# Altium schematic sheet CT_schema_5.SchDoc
size 522 x 390 mm
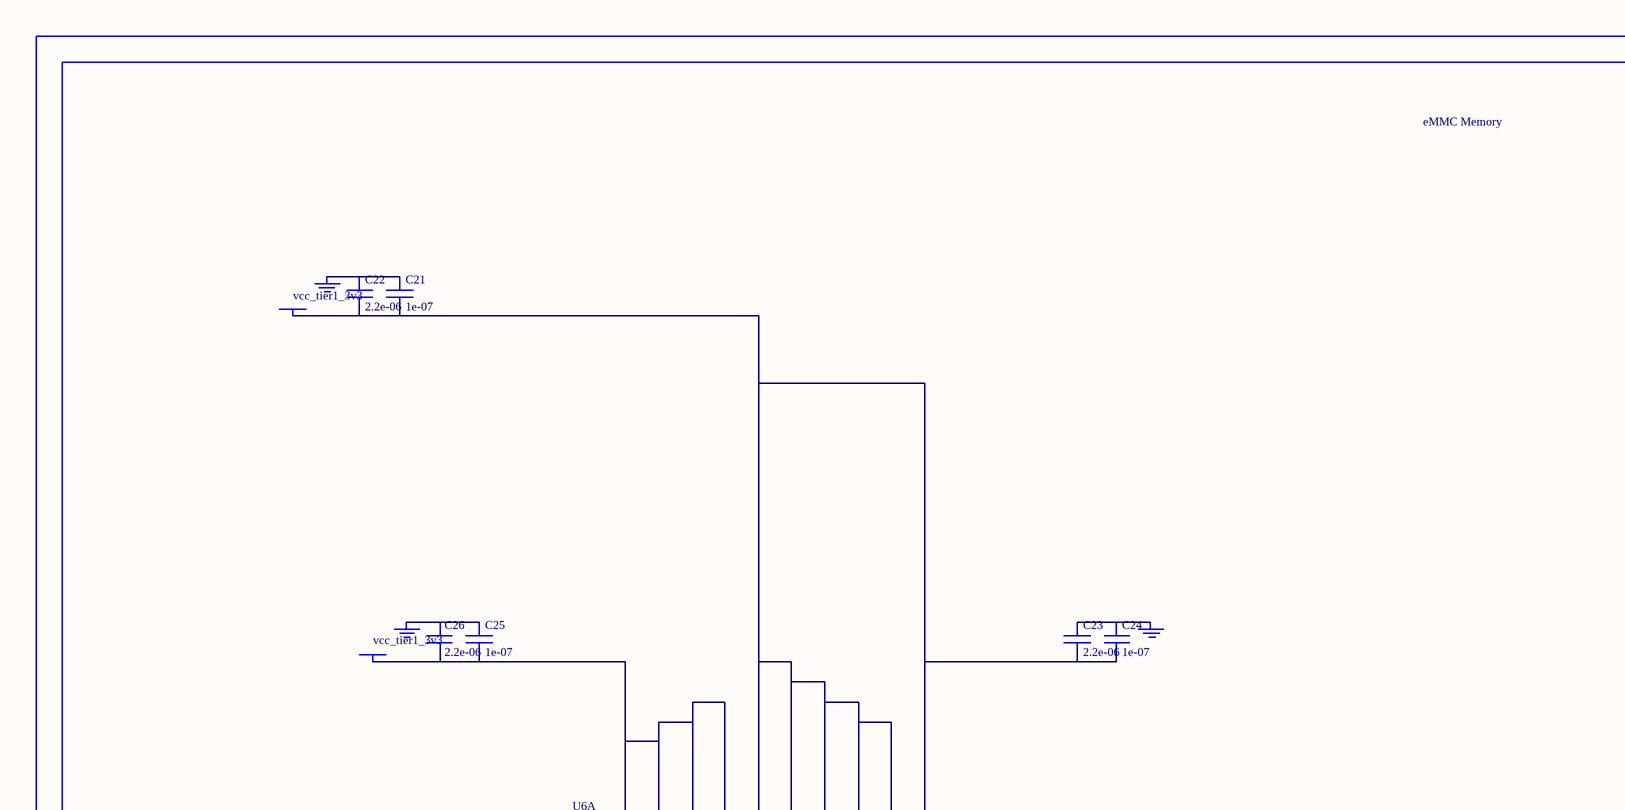
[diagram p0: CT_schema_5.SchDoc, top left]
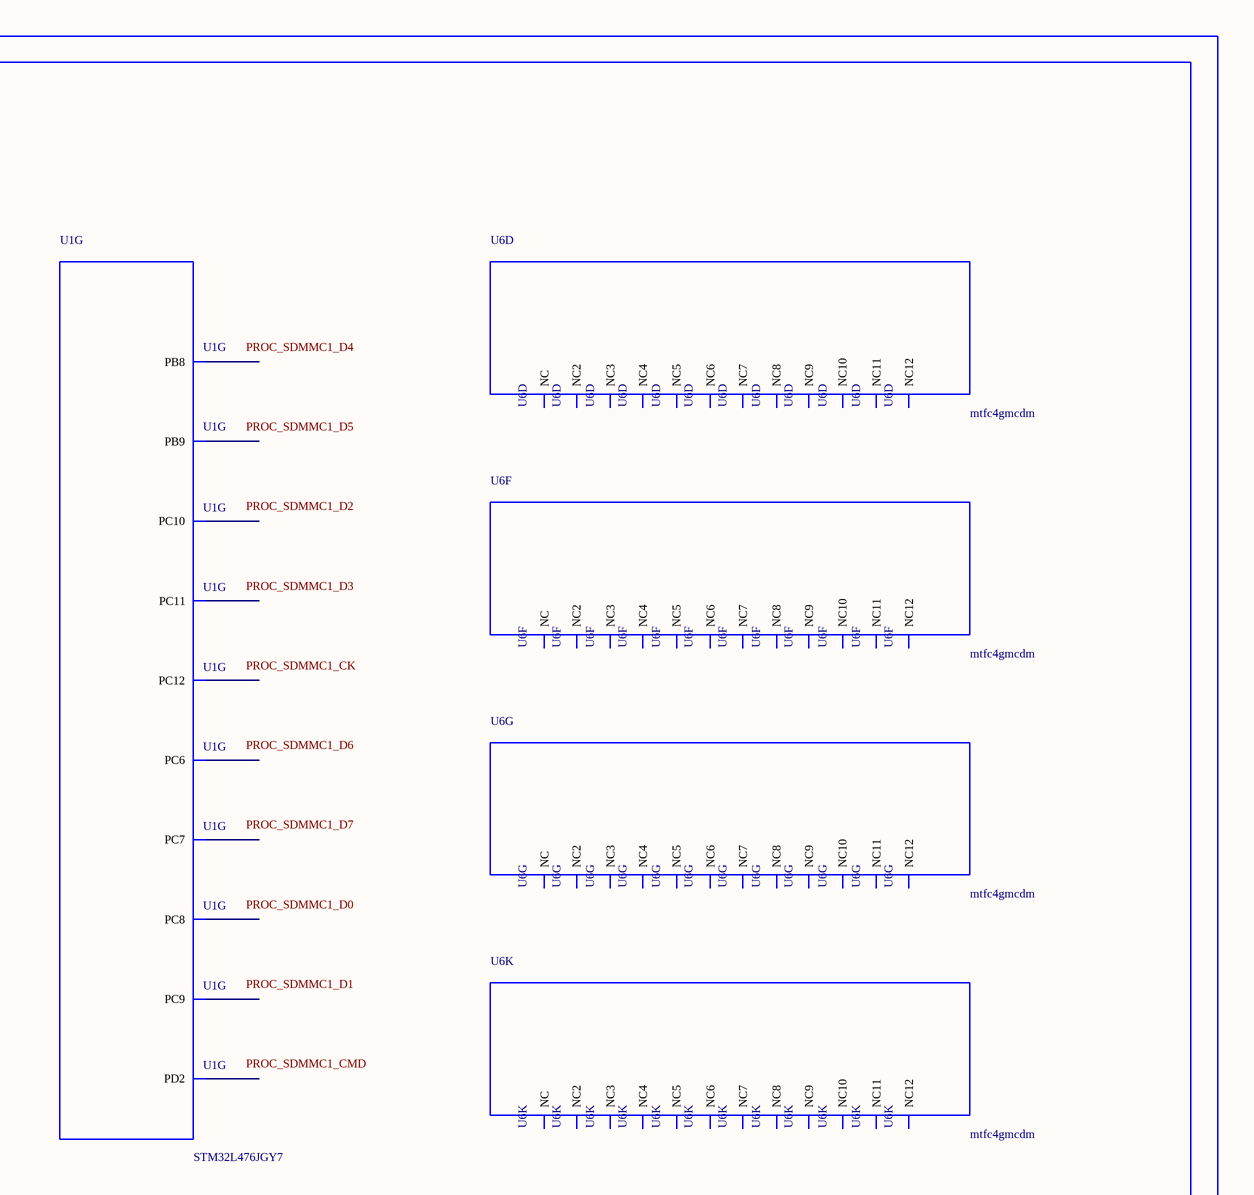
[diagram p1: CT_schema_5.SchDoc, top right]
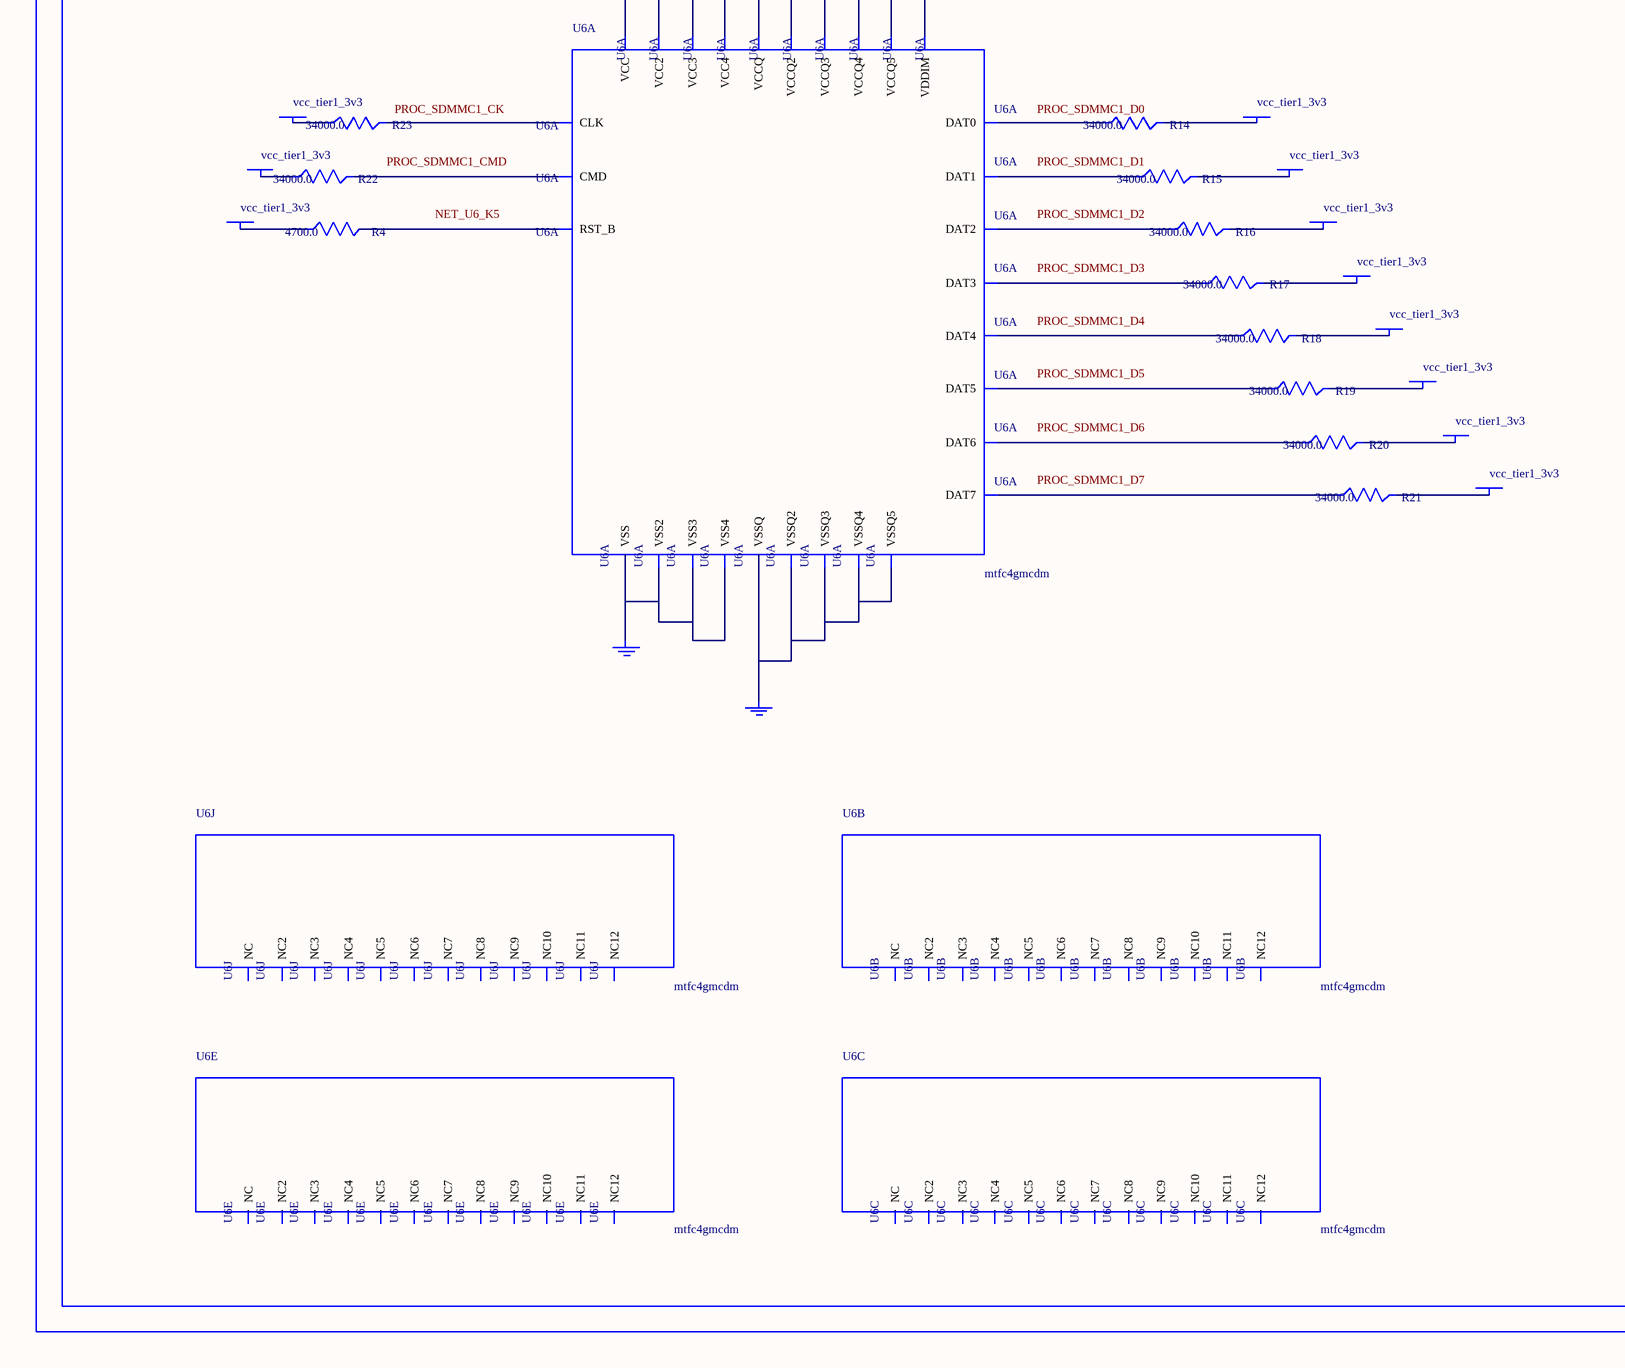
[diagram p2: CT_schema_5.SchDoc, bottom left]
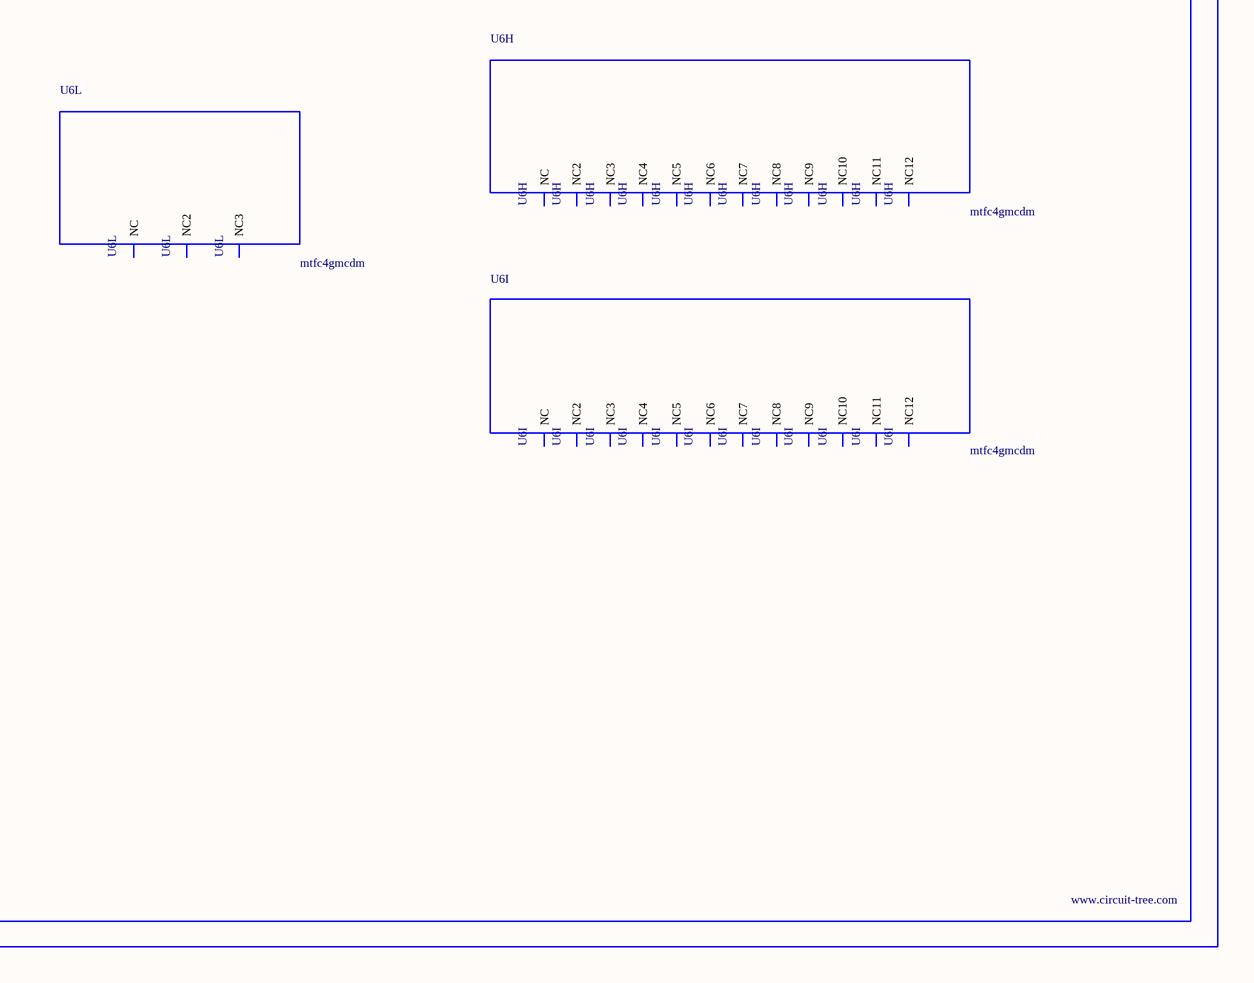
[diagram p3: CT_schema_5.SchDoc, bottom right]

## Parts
BORDER4  (no value)
C21  1e-07  [C0402]
C22  2.2e-06  [C0603]
C23  2.2e-06  [C0603]
C24  1e-07  [C0402]
C25  1e-07  [C0402]
C26  2.2e-06  [C0603]
GND_INSTANCE_4_0  (no value)
GND_INSTANCE_4_1  (no value)
GND_INSTANCE_4_2  (no value)
GND_INSTANCE_4_3  (no value)
GND_INSTANCE_4_4  (no value)
POWER_INSTANCE_4_0  vcc_tier1_3v3
POWER_INSTANCE_4_1  vcc_tier1_3v3
POWER_INSTANCE_4_2  vcc_tier1_3v3
POWER_INSTANCE_4_3  vcc_tier1_3v3
POWER_INSTANCE_4_4  vcc_tier1_3v3
POWER_INSTANCE_4_5  vcc_tier1_3v3
POWER_INSTANCE_4_6  vcc_tier1_3v3
POWER_INSTANCE_4_7  vcc_tier1_3v3
POWER_INSTANCE_4_8  vcc_tier1_3v3
POWER_INSTANCE_4_9  vcc_tier1_3v3
POWER_INSTANCE_4_10  vcc_tier1_3v3
POWER_INSTANCE_4_11  vcc_tier1_3v3
POWER_INSTANCE_4_12  vcc_tier1_3v3
R4  4700.0  [R0603]
R14  34000.0  [R0603]
R15  34000.0  [R0603]
R16  34000.0  [R0603]
R17  34000.0  [R0603]
R18  34000.0  [R0603]
R19  34000.0  [R0603]
R20  34000.0  [R0603]
R21  34000.0  [R0603]
R22  34000.0  [R0603]
R23  34000.0  [R0603]
U1  STM32L476JGY7  [WLCSP72]  (part G of 8)
U6  mtfc4gmcdm  [TFBGA-153]  (parts A,B,C,D,E,F,G,H,I,J,K,L of 12)

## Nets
NetC21_1: C21.1 C22.1 GND_INSTANCE_4_0.0(GND)
NetC21_2: C21.2 C22.2 C23.2 C24.2 POWER_INSTANCE_4_0.0(PWR) U6.C2(VDDIM) U6.C6(VCCQ) U6.M4(VCCQ2) U6.N4(VCCQ3) U6.P3(VCCQ4) U6.P5(VCCQ5)
NetC23_1: C23.1 C24.1 GND_INSTANCE_4_1.0(GND)
NetC25_1: C25.1 C26.1 GND_INSTANCE_4_2.0(GND)
NetC25_2: C25.2 C26.2 POWER_INSTANCE_4_1.0(PWR) U6.E6(VCC) U6.F5(VCC2) U6.J10(VCC3) U6.K9(VCC4)
NetGND_INSTANCE_4_3_0: GND_INSTANCE_4_3.0(GND) U6.E7(VSS) U6.G5(VSS2) U6.H10(VSS3) U6.K8(VSS4)
NetGND_INSTANCE_4_4_0: GND_INSTANCE_4_4.0(GND) U6.C4(VSSQ) U6.N2(VSSQ2) U6.N5(VSSQ3) U6.P4(VSSQ4) U6.P6(VSSQ5)
NetPOWER_INSTANCE_4_2_0: POWER_INSTANCE_4_2.0(PWR) R14.2
NetPOWER_INSTANCE_4_3_0: POWER_INSTANCE_4_3.0(PWR) R15.2
NetPOWER_INSTANCE_4_4_0: POWER_INSTANCE_4_4.0(PWR) R16.2
NetPOWER_INSTANCE_4_5_0: POWER_INSTANCE_4_5.0(PWR) R17.2
NetPOWER_INSTANCE_4_6_0: POWER_INSTANCE_4_6.0(PWR) R18.2
NetPOWER_INSTANCE_4_7_0: POWER_INSTANCE_4_7.0(PWR) R19.2
NetPOWER_INSTANCE_4_8_0: POWER_INSTANCE_4_8.0(PWR) R20.2
NetPOWER_INSTANCE_4_9_0: POWER_INSTANCE_4_9.0(PWR) R21.2
NetPOWER_INSTANCE_4_10_0: POWER_INSTANCE_4_10.0(PWR) R22.1
NetPOWER_INSTANCE_4_11_0: POWER_INSTANCE_4_11.0(PWR) R23.1
NetPOWER_INSTANCE_4_12_0: POWER_INSTANCE_4_12.0(PWR) R4.1
NetR4_2: R4.2 U6.K5(RST_B)
NetR14_1: R14.1 U6.A3(DAT0)
NetR15_1: R15.1 U6.A4(DAT1)
NetR16_1: R16.1 U6.A5(DAT2)
NetR17_1: R17.1 U6.B2(DAT3)
NetR18_1: R18.1 U6.B3(DAT4)
NetR19_1: R19.1 U6.B4(DAT5)
NetR20_1: R20.1 U6.B5(DAT6)
NetR21_1: R21.1 U6.B6(DAT7)
NetR22_2: R22.2 U6.M5(CMD)
NetR23_2: R23.2 U6.M6(CLK)

Not connected (* = marked no-connect by the designer): U1 A3(PD2) B3(PC12) C3(PC11) D3(PC10) E1(PC9) E7(PB8) E8(PB9) F1(PC7) F2(PC8) F3(PC6); U6 A1(NC) A2(NC7) A6(NC8) A7(NC9) A8(NC10) A9(NC11) A10(NC2) A11(NC3) A12(NC4) A13(NC5) A14(NC6) B1(NC12) B7(NC6) B8(NC7) B9(NC8) B10(NC) B11(NC2) B12(NC3) B13(NC4) B14(NC5) C1(NC9) C3(NC10) C5(NC11) C7(NC12) C8(NC6) C9(NC7) C10(NC) C11(NC2) C12(NC3) C13(NC4) C14(NC5) D1(NC8) D2(NC10) D3(NC11) D4(NC12) D12(NC9) D13(NC) D14(NC2) E1(NC3) E2(NC8) E3(NC9) E5(NC10) E8(NC11) E9(NC12) E10(NC4) E12(NC5) E13(NC6) E14(NC7) F1(NC) F2(NC6) F3(NC7) F10(NC2) F12(NC3) F13(NC4) F14(NC5) G1(NC8) G2(NC11) G3(NC12) G10(NC9) G12(NC10) G13(NC) G14(NC2) H1(NC3) H2(NC7) H3(NC8) H5(NC9) H12(NC4) H13(NC5) H14(NC6) J1(NC10) J2(NC11) J3(NC12) J5(NC4) J12(NC) J13(NC2) J14(NC3) K1(NC5) K2(NC9) K3(NC10) K6(NC11) K7(NC12) K10(NC6) K12(NC7) K13(NC8) K14(NC) L1(NC2) L2(NC6) L3(NC7) L12(NC3) L13(NC4) L14(NC5) M1(NC8) M2(NC9) M3(NC10) M7(NC11) M8(NC12) M9(NC6) M10(NC) M11(NC2) M12(NC3) M13(NC4) M14(NC5) N1(NC7) N3(NC8) N6(NC9) N7(NC10) N8(NC11) N9(NC12) N10(NC) N11(NC2) N12(NC3) N13(NC4) N14(NC5) P1(NC6) P2(NC9) P7(NC10) P8(NC11) P9(NC12) P10(NC7) P11(NC8) P12(NC) P13(NC2) P14(NC3)

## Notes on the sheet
- Labels drawn without touching a wire or pin: NET_U6_K5, PROC_SDMMC1_CK, PROC_SDMMC1_CMD, PROC_SDMMC1_D0, PROC_SDMMC1_D1, PROC_SDMMC1_D2, PROC_SDMMC1_D3, PROC_SDMMC1_D4, PROC_SDMMC1_D5, PROC_SDMMC1_D6, PROC_SDMMC1_D7

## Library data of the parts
BORDER4 = BORDER_PAGE4
C21 C24 C25 = C0402C104K3RACTU
C22 C23 C26 = C0603C225K8RACTU
GND_INSTANCE_4_0-GND_INSTANCE_4_4 = GND
POWER_INSTANCE_4_0-POWER_INSTANCE_4_12 = PWR
R4 = RC0603JR-074K7L
R14-R23 = ERA3ARB3402V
